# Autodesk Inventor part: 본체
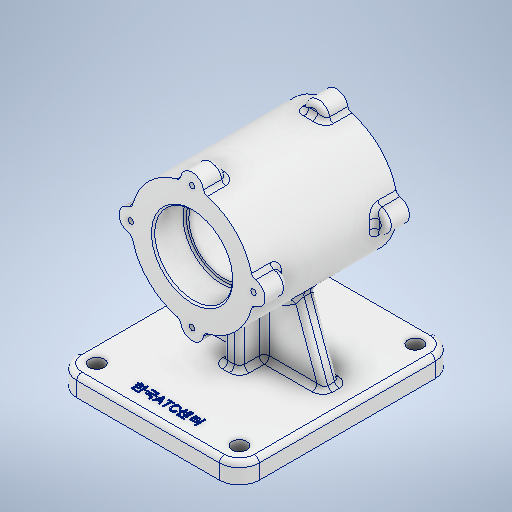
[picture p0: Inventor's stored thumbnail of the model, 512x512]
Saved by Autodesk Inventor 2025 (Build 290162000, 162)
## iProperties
Created: 2024-08
Part Number: 본체
Material: 알루미늄 6061
Document SubType Name: Modeling
Designer: onair
Density: 2.7 g/cm^3
Appearance: 알루미늄 - 평지
Mass: 1215.39 g
Surface Area: 796.909 cm^2
Volume: 450.146 cm^3
Author: onair
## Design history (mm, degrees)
sketch "스케치1"
  geometry: L1 (43, 65)-(-43, 65); L2 (-55, 53)-(-55, -53); L3 (-43, -65)-(43, -65); L4 (55, -53)-(55, 53); L5 (55, 65)-(-55, -65); L6 (-55, 65)-(55, -65); A1 r 12 centre (43, 53) between (55, 53) and (43, 65); A2 r 12 centre (-43, 53) between (-43, 65) and (-55, 53); A3 r 12 centre (-43, -53) between (-55, -53) and (-43, -65); A4 r 12 centre (43, -53) between (43, -65) and (55, -53); 1 further point
  constraints: 12 end point, 8 point on circle, 8 point on line, 8 tangent, 4 centre point, 3 equal radius, 2 midpoint, 2 parallel, 1 horizontal, 1 perpendicular
  dimensions: "d0" = 130 distance of L6.start L5.end; "d1" = 110 distance of L5.end L6.end; "d2" = 12 radius of A1
extrude "돌출1" new body sketch "스케치1" distance "d3" = 12; taper "d4" = 0 deg
sketch "스케치2"
  geometry: A1 r 12 centre (-43, 53) between (-43, 65) and (-55, 53) reference; A2 r 12 centre (43, 53) between (55, 53) and (43, 65) reference; A3 r 12 centre (43, -53) between (43, -65) and (55, -53) reference; A4 r 12 centre (-43, -53) between (-55, -53) and (-43, -65) reference; 5 further points
  constraints: 4 coincident
hole "구멍1" sketch "스케치2" at (-43, 53), (43, 53), (43, -53), (-43, -53) diameter "d5" = 9; stored, may be unused: countersink angle "d9" = 90 deg, drill point angle "d11" = 120 deg; dims "d6" = 8, "d7" = 4, "d8" = 2, "d10" = 10
node "작업 평면1"
sketch "스케치4"
  geometry: L1 (43, -27.058)-(43, 162.351) reference; L2 (0, 0)-(86, 0) reference; C1 r 37 at (43, 82); 2 further points
  constraints: 1 centre point, 1 midpoint, 1 point on line
  dimensions: "d15" = 37 radius of C1; "d16" = 82 distance of point (43, 0) C1.centre
extrude "돌출2" join sketch "스케치4" stored distance "d17" = 87; taper "d18" = 0 deg
sketch "스케치5"
  geometry: L1 (137.943, -5)-(-51.616, -5); L2 (0, 65)-(12, 65) reference; L3 (45, -48.5)-(119, -48.5) reference; L4 (119, 38.5)-(45, 38.5) reference; L5 (82, 74.731)-(82, -76.192); L6 (0, -106.377)-(0, 104.915) reference; L7 (105.5, 38.5)-(82, 38.5); L8 (82, 38.5)-(82, 19.5); L9 (82, 19.5)-(104.5, 19.5); L10 (105.5, 20.5)-(105.5, 38.5); L11 (103, 19.5)-(82, 19.5); L12 (82, 19.5)-(82, -29.5); L13 (82, -29.5)-(103, -29.5); L14 (103, -29.5)-(103, 19.5); L15 (105.5, -30.5)-(105.5, -48.5); L16 (82, -29.5)-(104.5, -29.5); L17 (105.5, -48.5)-(82, -48.5); L18 (82, -48.5)-(82, -29.5); A1 r 1 centre (104.5, 20.5) between (104.5, 19.5) and (105.5, 20.5); A2 r 1 centre (104.5, -30.5) between (105.5, -30.5) and (104.5, -29.5); 7 further points
  constraints: 28 end point, 8 point on line, 4 parallel, 4 point on circle, 4 symmetric about line, 4 tangent, 3 horizontal, 2 centre point, 2 perpendicular, 1 equal radius, 1 vertical, 1 other
  dimensions: "d19" = 70 distance between parallel lines of L2 L1; "d20" = 82 distance between parallel lines of L6 L5; "d21" = 19 distance of point (105.5, 19.5) L7.start; "d22" = 47 diameter of L10 L5; "d23" = 42 diameter of L14 L5; "d24" = 1 radius of A1
revolve "회전1" sketch "스케치5" stored, may be unused: angle "d25" = 90 deg
chamfer "모따기1" distance "d26" = 1; stored, may be unused: second distance "d27" = 2, angle "d28" = 45 deg
sketch "스케치6"
  geometry: L1 (0, -105.8)-(0, 60.8) reference; C1 r 7 at (0, 37); 2 further points
  constraints: 1 centre point, 1 point on line, 1 vertical alignment, 1 other
  dimensions: "d29" = 7 radius of C1
extrude "돌출3" join sketch "스케치6" distance "d30" = 14; taper "d31" = 0 deg
fillet "모깎기1" dims "d35" = 3
fillet "모깎기2" dims "d36" = 3
sketch "스케치7" dims "d37" = 37
  geometry: L1 (43, -25.2)-(43, 151.2) reference; C1 r 24.5 at (43, 82) reference; 3 further points
  constraints: 1 coincident, 1 point on line, 1 vertical alignment, 2 other
hole "구멍2" sketch "스케치7" at (43, 119) diameter "d38" = 3.242; stored, may be unused: countersink angle "d42" = 82 deg, drill point angle "d44" = 120 deg; dims "d39" = 8, "d40" = 3.023, "d41" = 2, "d43" = 10
sketch "스케치8"
  geometry: L1 (81.5, 0)-(81.5, 12) reference; L2 (81.5, 0)-(81.5, 12) reference; L3 (-4.5, 12)-(4.5, 12) reference; L4 (81.5, 12)-(90.5, 12) reference; L5 (81.5, 12)-(90.5, 12) reference; L6 (-4.5, 12)-(4.5, 12) reference; L7 (86, 12)-(98, 12) reference; L8 (98, 12)-(86, 12) reference; L9 (86, 12)-(0, 12) reference; L10 (0, 12)-(-12, 12) reference; L11 (-12, 12)-(0, 12) reference; L12 (0, 12)-(86, 12) reference; L13 (84, 12)-(67.161, 58.264); L14 (98, 0)-(98, 12) reference; L15 (43, 92.388)-(43, -14.668); L16 (2, 12)-(18.839, 58.264); C1 r 21 at (43, 82) reference; 1 further point
  constraints: 6 end point, 2 point on line, 2 symmetric about line, 1 vertical
  dimensions: "d48" = 110 deg angle of L12 L13; "d49" = 14 distance from line of L14 L13.start
  node "투영된 루프3"
sketch "스케치9"
  geometry: L1 (-5, -15)-(5, -15); L2 (5, -15)-(5, 25); L3 (5, 25)-(-5, 25); L4 (-5, 25)-(-5, -15); L5 (0, 91)-(0, -91) reference; L6 (-43, -65)-(43, -65) reference; 1 further point
  constraints: 8 end point, 2 parallel, 1 horizontal, 1 perpendicular, 1 other
  dimensions: "d50" = 10 distance of L2.end L3.end; "d51" = 40 distance of L3.end L1.start; "d52" = 50 distance between parallel lines of L6 L1
extrude "돌출4" join sketch "스케치9" stored distance "d53" = 14; taper "d54" = 0 deg
fillet "모깎기3" dims "d55" = 3
feature "리브1" dims "d57" = 1, "d58" = 10, "d59" = 0, "d60" = 0, "d61" = 1, "d62" = 1
feature "리브2" dims "d63" = 1, "d64" = 10, "d65" = 0, "d66" = 0, "d67" = 1, "d68" = 1
fillet "모깎기5" dims "d69" = 3
fillet "모깎기6" dims "d70" = 3
fillet "모깎기7" dims "d71" = 3
sketch "스케치10"
  geometry: L1 (-43, -65)-(43, -65) reference; L2 (0, 91)-(0, -91) reference; 2 further points
  constraints: 1 point on line, 1 other
  dimensions: "d72" = 12 distance from line of L1 point (0, -53)
feature "엠보싱1" sketch "스케치10" dims "d0" = 130, "d1" = 110, "d2" = 12, "d73" = 0.5, "d74" = 0
node "솔리드1"
pattern_circular "원형 패턴1" dims angle "d33" = 360 deg
mirror "미러1"
pattern_circular "원형 패턴2" dims angle "d46" = 360 deg
mirror "미러2"
node "투영된 루프2"
feature "A9D066F2-1C7D-4E18-AEED-F7BC21143FA4" dims "d5" = 9, "d6" = 8, "d7" = 4, "d8" = 2, "d9" = 90 deg, "d10" = 10, "d11" = 120 deg
